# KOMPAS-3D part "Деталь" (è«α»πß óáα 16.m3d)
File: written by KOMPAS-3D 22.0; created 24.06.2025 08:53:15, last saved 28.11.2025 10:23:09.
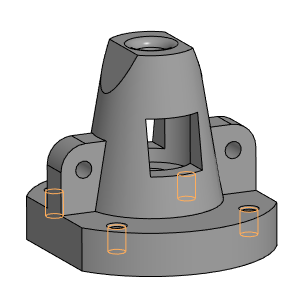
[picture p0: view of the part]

Document properties: Автор: alymovy@yandex.ru; Организация: HP; Полное имя файла: Корпус вар 16.cdw

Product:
- Part/product: Деталь
    Материал: Фторопласт-4 ГОСТ 10007-80 Е (density 2200 kg/m3)
    Масса: 1.228349
    Форматы листов документа: A3

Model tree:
1. Эскиз:1
2. Элемент выдавливания:1
     Расстояние 2 = 25
3. Эскиз:2  (with: Элемент выдавливания:1)
4. Элемент вращения:1
     Угол 1 = 360
5. Эскиз:3  (with: Элемент выдавливания:1)
6. Ребро жесткости:1
     Толщина стенки 1 = 18; Толщина стенки 2 = 1
7. Зеркальный массив:1
8. Экземпляр ( 1 )
9. Экземпляр ( 2 )  (with: Ребро жесткости:1)
10. Эскиз:4  (with: Элемент вращения:1)
11. Элемент вращения:2
     Угол 1 = 360
12. Эскиз:5  (with: Элемент вращения:1)
13. Элемент выдавливания:2
     Расстояние 1 = 70
14. Эскиз:6  (with: Элемент вращения:1)
15. Элемент выдавливания:3
     Расстояние 1 = 70
16. Эскиз:7  (with: Ребро жесткости:1, Элемент выдавливания:1)
17. Элемент выдавливания:4
18. Эскиз:8  (with: Элемент выдавливания:1, Элемент вращения:1)
19. Отверстие:1  (with: Элемент выдавливания:1, Ребро жесткости:1)  (labels: M10)
     Глубина выреза = 20; Диаметр отверстия = 8.3762; Угол конуса дна = 118; Расстояние 1 = -31.6586; Расстояние 2 = 19.3414; Диаметр зенковки = 11.5762; Глубина зенковки = 1.6; Угол зенковки = 90
20. M10  (labels: cil0_24705-2004 coarse)
     Длина резьбы = 15; Шаг резьбы = 1.5; Номинальный диаметр резьбы = 10
21. Зеркальный массив:2  (with: Экземпляр ( 1 ), Экземпляр ( 2 ), Отверстие:1)
22. Зеркальный массив:3  (with: Экземпляр ( 1 ), Экземпляр ( 2 ), Зеркальный массив:2, Отверстие:1)
23. Экземпляр ( 2 )  (with: Отверстие:1)
24. Скругление:1  (with: Элемент вращения:2)  (labels: Фторопласт-4 ГОСТ 10007-80 Е)
     Радиус = 5

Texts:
  Точка начала. Х
  Точка начала. Y
  Точка начала. Z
